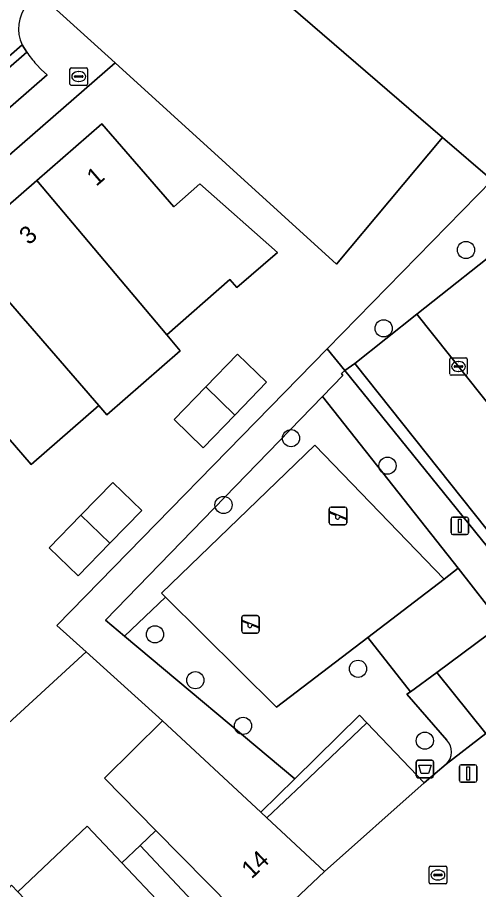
# Model space of a CAD drawing. Extents: x 161881 to 162523, y 381678 to 382381.
# Drawn here: x 162089.24 to 162115.53, y 382087.64 to 382137.32 of the extents above; entities that cross this region are included whole.
import ezdxf

# ---------------------------------------------------------------- set-up
doc = ezdxf.new("R2010")
doc.units = 0
for name, color, linetype in [('IMGEO_Afvalbak', 7, 'Continuous'), ('IMGEO_Boom', 7, 'Continuous'), ('IMGEO_Erf', 7, 'Continuous'), ('IMGEO_Groenvoorziening', 7, 'Continuous'), ('IMGEO_Hek', 7, 'Continuous'), ('IMGEO_Kolk', 7, 'Continuous'), ('IMGEO_Lichtmast', 7, 'Continuous'), ('IMGEO_Pand', 7, 'Continuous'), ('IMGEO_Pand_nummerreeks', 7, 'Continuous'), ('IMGEO_Pand_overbouw', 7, 'Continuous'), ('IMGEO_Parkeervlak_open', 7, 'Continuous'), ('IMGEO_Rijbaan_lokaal_open', 7, 'Continuous'), ('IMGEO_Speelvoorziening', 7, 'Continuous'), ('IMGEO_Terreindeel_zand', 7, 'Continuous'), ('IMGEO_Voetpad_open', 7, 'Continuous'), ('IMGEO_Woonerf_open', 7, 'Continuous')]:
    doc.layers.add(name, color=color, linetype=linetype)

msp = doc.modelspace()

# ---------------------------------------------------------------- linework, layer by layer
at = {"layer": 'IMGEO_Afvalbak'}
for p, q in [((162111.976, 382094.108), (162111.976, 382094.908)), ((162111.976, 382094.908), (162111.976, 382094.108)), ((162112.076, 382095.008), (162112.866, 382095.008)), ((162112.866, 382095.008), (162112.076, 382095.008)), ((162112.966, 382094.908), (162112.966, 382094.108)), ((162112.966, 382094.108), (162112.966, 382094.908)), ((162112.866, 382094.008), (162112.076, 382094.008)), ((162112.076, 382094.008), (162112.866, 382094.008))]:
    msp.add_line(p, q, dxfattribs=at)
msp.add_lwpolyline([(162112.119, 382094.722), (162112.823, 382094.722), (162112.674, 382094.252), (162112.268, 382094.252), (162112.119, 382094.722)], dxfattribs=at)
for centre, start, end in [((162112.076, 382094.908), 90, 180), ((162112.076, 382094.908), 90, 180), ((162112.866, 382094.908), 0, 90), ((162112.866, 382094.908), 360, 90), ((162112.076, 382094.108), 180, 270), ((162112.076, 382094.108), 180, 270), ((162112.866, 382094.108), 270, 0), ((162112.866, 382094.108), 270, 0)]:
    msp.add_arc(centre, 0.1, start, end, dxfattribs=at)
at = {"layer": 'IMGEO_Boom'}
for centre in [(162114.816, 382124.076), (162110.121, 382119.608), (162104.84, 382113.352), (162110.34, 382111.786), (162100.992, 382109.55), (162097.081, 382102.174), (162108.659, 382100.216), (162099.384, 382099.563), (162102.103, 382096.961), (162112.468, 382096.118)]:
    msp.add_circle(centre, 0.489, dxfattribs=at)
at = {"layer": 'IMGEO_Erf'}
for points in [[(162116.187, 382169.927), (162097.305, 382146.167), (162098.125, 382145.533), (162097.277, 382144.452), (162113.475, 382130.48), (162116.309, 382128.058)], [(162084.713, 382093.447), (162093.161, 382101.174), (162091.485, 382102.685), (162106.899, 382118.44), (162116.309, 382128.058), (162113.475, 382130.48), (162107.435, 382123.266), (162094.812, 382134.731), (162045.016, 382091.412)], [(162086.012, 382124.267), (162090.338, 382128.029), (162094.053, 382131.261), (162098.156, 382126.533), (162099.648, 382127.839), (162104.067, 382123.934), (162101.751, 382121.938), (162101.356, 382122.39), (162097.758, 382119.243), (162098.524, 382118.336), (162094.336, 382114.689), (162093.878, 382115.216), (162090.02, 382111.857), (162088.706, 382113.366)], [(162102.969, 382085.099), (162097.133, 382091.008), (162094.202, 382093.977), (162097.513, 382097.25), (162093.161, 382101.174), (162084.713, 382093.447), (162084.873, 382093.288), (162083.164, 382091.402), (162082.836, 382091.728), (162082.663, 382091.572), (162066.905, 382077.16)], [(162086.522, 382085.22), (162088.893, 382087.889), (162089.263, 382087.5), (162093.223, 382091.242), (162095.194, 382089.156), (162097.49, 382086.726)]]:
    msp.add_lwpolyline(points, dxfattribs=at)
for points in [[(162099.984, 382116.273), (162101.79, 382118.138), (162103.437, 382116.541), (162101.635, 382114.674), (162099.835, 382112.81), (162098.178, 382114.409)], [(162094.674, 382110.831), (162096.324, 382109.236), (162094.504, 382107.365), (162092.695, 382105.507), (162091.043, 382107.115), (162092.859, 382108.973)]]:
    msp.add_lwpolyline(points, close=True, dxfattribs=at)
at = {"layer": 'IMGEO_Groenvoorziening'}
for points in [[(162132.956, 382116.323), (162132.796, 382116.521), (162129.478, 382119.862), (162126.569, 382122.976), (162126.247, 382123.32), (162123.474, 382126.921), (162120.058, 382131.359), (162116.536, 382127.884), (162116.309, 382128.058), (162106.899, 382118.44), (162107.907, 382117.216), (162108.469, 382117.615), (162112.012, 382120.419), (162117.385, 382124.671), (162120.906, 382127.458), (162133.886, 382111.152), (162130.444, 382108.362), (162129.686, 382107.748), (162130.473, 382106.822), (162136.002, 382111.248), (162136.61, 382110.616), (162137.218, 382111.056)], [(162095.334, 382102.076), (162094.256, 382102.976), (162106.628, 382115.719), (162107.794, 382116.925), (162107.71, 382117.031), (162107.907, 382117.216), (162106.899, 382118.44), (162091.485, 382102.685), (162093.161, 382101.174), (162097.513, 382097.25), (162103.117, 382092.038), (162105.064, 382093.949)], [(162114.38, 382105.944), (162106.628, 382115.719), (162094.256, 382102.976), (162095.334, 382102.076), (162097.688, 382104.296), (162097.457, 382104.526), (162106.206, 382112.964), (162113.565, 382105.319)]]:
    msp.add_lwpolyline(points, close=True, dxfattribs=at)
for points in [[(162117.466, 382096.317), (162118.006, 382096.754), (162117.215, 382097.756), (162119.049, 382099.221), (162119.843, 382098.237), (162119.991, 382098.357), (162121.505, 382099.58), (162122.028, 382100.003), (162126.539, 382103.647), (162125.726, 382104.611), (162125.058, 382104.075), (162121.513, 382101.233), (162121.424, 382101.345), (162121, 382101.024), (162107.907, 382117.216), (162107.71, 382117.031), (162107.794, 382116.925), (162106.628, 382115.719), (162114.38, 382105.944), (162116.87, 382102.749), (162113.15, 382100.011), (162115.951, 382096.535)], [(162111.445, 382098.77), (162111.653, 382098.909), (162109.226, 382101.989), (162104.008, 382098.021), (162097.688, 382104.296), (162095.334, 382102.076), (162105.064, 382093.949), (162108.747, 382097.564), (162109.165, 382097.128), (162112.431, 382093.718), (162113.69, 382094.776)], [(162113.725, 382096.155), (162111.445, 382098.77)]]:
    msp.add_lwpolyline(points, dxfattribs=at)
msp.add_arc((162113.018, 382095.483), 0.976, 313.5594, 43.5328, dxfattribs=at)
at = {"layer": 'IMGEO_Hek'}
for points in [[(162106.899, 382118.44), (162107.907, 382117.216)], [(162107.907, 382117.216), (162107.71, 382117.031), (162107.794, 382116.925)]]:
    msp.add_lwpolyline(points, dxfattribs=at)
at = {"layer": 'IMGEO_Kolk'}
for p, q in [((162092.231, 382133.53), (162092.231, 382134.382)), ((162092.306, 382134.456), (162093.158, 382134.456)), ((162092.719, 382134.236), (162092.744, 382134.236)), ((162093.232, 382134.382), (162093.232, 382133.53)), ((162092.49, 382133.95), (162092.49, 382133.962)), ((162092.928, 382133.913), (162092.53, 382133.913)), ((162092.533, 382133.999), (162092.931, 382133.999)), ((162092.742, 382133.676), (162092.717, 382133.676)), ((162092.974, 382133.962), (162092.974, 382133.95)), ((162093.158, 382133.456), (162092.306, 382133.456)), ((162113.889, 382117.01), (162113.889, 382117.862)), ((162113.964, 382117.936), (162114.816, 382117.936)), ((162114.89, 382117.862), (162114.89, 382117.01)), ((162114.148, 382117.43), (162114.148, 382117.442)), ((162114.586, 382117.393), (162114.188, 382117.393)), ((162114.191, 382117.479), (162114.589, 382117.479)), ((162114.377, 382117.716), (162114.402, 382117.716)), ((162114.632, 382117.442), (162114.632, 382117.43)), ((162114.816, 382116.936), (162113.964, 382116.936)), ((162114.4, 382117.156), (162114.375, 382117.156)), ((162112.792, 382088.966), (162113.644, 382088.966)), ((162112.717, 382088.04), (162112.717, 382088.892)), ((162112.976, 382088.46), (162112.976, 382088.472)), ((162113.414, 382088.423), (162113.016, 382088.423)), ((162113.019, 382088.509), (162113.417, 382088.509)), ((162113.205, 382088.746), (162113.23, 382088.746)), ((162113.46, 382088.472), (162113.46, 382088.46)), ((162113.718, 382088.892), (162113.718, 382088.04)), ((162113.644, 382087.966), (162112.792, 382087.966)), ((162113.228, 382088.186), (162113.203, 382088.186))]:
    msp.add_line(p, q, dxfattribs=at)
for points in [[(162092.231, 382133.53), (162092.231, 382134.382)], [(162092.306, 382134.456), (162093.158, 382134.456)], [(162093.232, 382134.382), (162093.232, 382133.53)], [(162093.158, 382133.456), (162092.306, 382133.456)], [(162113.889, 382117.01), (162113.889, 382117.862)], [(162113.964, 382117.936), (162114.816, 382117.936)], [(162114.89, 382117.862), (162114.89, 382117.01)], [(162114.816, 382116.936), (162113.964, 382116.936)], [(162112.792, 382088.966), (162113.644, 382088.966)], [(162112.717, 382088.04), (162112.717, 382088.892)], [(162113.718, 382088.892), (162113.718, 382088.04)], [(162113.644, 382087.966), (162112.792, 382087.966)]]:
    msp.add_lwpolyline(points, dxfattribs=at)
for centre, radius, start, end in [((162092.308, 382134.38), 0.0765, 91.552, 178.448), ((162092.308, 382134.38), 0.0765, 91.552, 178.448), ((162093.156, 382134.38), 0.0765, 1.552, 88.448), ((162093.156, 382134.38), 0.0765, 1.552, 88.448), ((162092.53, 382133.959), 0.0403, 85.8775, 175.7526), ((162092.527, 382133.949), 0.0366, 178.938, 274.7102), ((162092.931, 382133.956), 0.043, 264.8664, 352.4533), ((162092.935, 382133.961), 0.0386, 1.7309, 96.639), ((162092.308, 382133.532), 0.0765, 181.552, 268.448), ((162092.308, 382133.532), 0.0765, 181.552, 268.448), ((162093.156, 382133.532), 0.0765, 271.552, 358.448), ((162093.156, 382133.532), 0.0765, 271.552, 358.448), ((162113.966, 382117.86), 0.0765, 91.552, 178.448), ((162113.966, 382117.86), 0.0765, 91.552, 178.448), ((162114.814, 382117.86), 0.0765, 1.552, 88.448), ((162114.814, 382117.86), 0.0765, 1.552, 88.448), ((162114.188, 382117.439), 0.0403, 85.8775, 175.7526), ((162114.185, 382117.429), 0.0366, 178.938, 274.7102), ((162114.589, 382117.436), 0.043, 264.8664, 352.4533), ((162114.593, 382117.441), 0.0386, 1.7309, 96.639), ((162113.966, 382117.012), 0.0765, 181.552, 268.448), ((162113.966, 382117.012), 0.0765, 181.552, 268.448), ((162114.814, 382117.012), 0.0765, 271.552, 358.448), ((162114.814, 382117.012), 0.0765, 271.552, 358.448), ((162112.794, 382088.89), 0.0765, 91.552, 178.448), ((162112.794, 382088.89), 0.0765, 91.552, 178.448), ((162113.642, 382088.89), 0.0765, 1.552, 88.448), ((162113.642, 382088.89), 0.0765, 1.552, 88.448), ((162113.016, 382088.469), 0.0403, 85.8775, 175.7526), ((162113.013, 382088.459), 0.0366, 178.938, 274.7102), ((162113.417, 382088.466), 0.043, 264.8664, 352.4533), ((162113.421, 382088.471), 0.0386, 1.7309, 96.639), ((162112.794, 382088.042), 0.0765, 181.552, 268.448), ((162112.794, 382088.042), 0.0765, 181.552, 268.448), ((162113.642, 382088.042), 0.0765, 271.552, 358.448), ((162113.642, 382088.042), 0.0765, 271.552, 358.448)]:
    msp.add_arc(centre, radius, start, end, dxfattribs=at)
for centre, major_axis, ratio, start_param, end_param in [((162092.718, 382133.956), (-0.387, 0.002), 0.722429, 4.712389, 7.853982), ((162092.743, 382133.956), (-0.39, 0.002), 0.717154, 1.570796, 4.712389), ((162114.376, 382117.436), (-0.387, 0.002), 0.722429, 4.712389, 7.853982), ((162114.401, 382117.436), (-0.39, 0.002), 0.717154, 1.570796, 4.712389), ((162113.204, 382088.466), (-0.387, 0.002), 0.722429, 4.712389, 7.853982), ((162113.229, 382088.466), (-0.39, 0.002), 0.717154, 1.570796, 4.712389)]:
    msp.add_ellipse(centre, major_axis=major_axis, ratio=ratio, start_param=start_param, end_param=end_param, dxfattribs=at)
at = {"layer": 'IMGEO_Lichtmast'}
for p, q in [((162114.064, 382108.862), (162114.854, 382108.862)), ((162114.854, 382108.862), (162114.064, 382108.862)), ((162113.964, 382107.962), (162113.964, 382108.762)), ((162113.964, 382108.762), (162113.964, 382107.962)), ((162114.954, 382108.762), (162114.954, 382107.962)), ((162114.954, 382107.962), (162114.954, 382108.762)), ((162114.854, 382107.862), (162114.064, 382107.862)), ((162114.064, 382107.862), (162114.854, 382107.862)), ((162114.439, 382093.847), (162114.439, 382094.647)), ((162114.439, 382094.647), (162114.439, 382093.847)), ((162114.539, 382094.747), (162115.329, 382094.747)), ((162115.329, 382094.747), (162114.539, 382094.747)), ((162115.429, 382094.647), (162115.429, 382093.847)), ((162115.429, 382093.847), (162115.429, 382094.647)), ((162115.329, 382093.747), (162114.539, 382093.747)), ((162114.539, 382093.747), (162115.329, 382093.747))]:
    msp.add_line(p, q, dxfattribs=at)
for points in [[(162114.384, 382108.737), (162114.534, 382108.737), (162114.534, 382107.987), (162114.384, 382107.987), (162114.384, 382108.737)], [(162114.859, 382094.622), (162115.009, 382094.622), (162115.009, 382093.872), (162114.859, 382093.872), (162114.859, 382094.622)]]:
    msp.add_lwpolyline(points, dxfattribs=at)
for centre, start, end in [((162114.064, 382108.762), 90, 180), ((162114.064, 382108.762), 90, 180), ((162114.854, 382108.762), 0, 90), ((162114.854, 382108.762), 360, 90), ((162114.064, 382107.962), 180, 270), ((162114.064, 382107.962), 180, 270), ((162114.854, 382107.962), 270, 0), ((162114.854, 382107.962), 270, 0), ((162114.539, 382094.647), 90, 180), ((162114.539, 382094.647), 90, 180), ((162115.329, 382094.647), 0, 90), ((162115.329, 382094.647), 360, 90), ((162114.539, 382093.847), 180, 270), ((162114.539, 382093.847), 180, 270), ((162115.329, 382093.847), 270, 0), ((162115.329, 382093.847), 270, 0)]:
    msp.add_arc(centre, 0.1, start, end, dxfattribs=at)
at = {"layer": 'IMGEO_Pand'}
for points in [[(162097.277, 382144.452), (162097.156, 382144.557), (162091.265, 382137.952), (162094.812, 382134.731), (162107.435, 382123.266), (162113.475, 382130.48)], [(162098.156, 382126.533), (162094.053, 382131.261), (162090.338, 382128.029), (162097.758, 382119.243), (162101.356, 382122.39), (162101.751, 382121.938), (162104.067, 382123.934), (162099.648, 382127.839)], [(162090.338, 382128.029), (162086.012, 382124.267), (162093.878, 382115.216), (162094.336, 382114.689), (162098.524, 382118.336), (162097.758, 382119.243)], [(162086.012, 382124.267), (162082.144, 382120.902), (162088.706, 382113.366), (162090.02, 382111.857), (162093.878, 382115.216)], [(162101.79, 382118.138), (162099.984, 382116.273), (162101.635, 382114.674), (162103.437, 382116.541)], [(162101.635, 382114.674), (162099.984, 382116.273), (162098.178, 382114.409), (162099.835, 382112.81)], [(162094.674, 382110.831), (162092.859, 382108.973), (162094.504, 382107.365), (162096.324, 382109.236)], [(162092.859, 382108.973), (162091.043, 382107.115), (162092.695, 382105.507), (162094.504, 382107.365)], [(162103.466, 382091.714), (162103.117, 382092.038), (162097.513, 382097.25), (162094.202, 382093.977), (162097.133, 382091.008), (162102.969, 382085.099), (162106.745, 382088.664)], [(162097.49, 382086.726), (162095.194, 382089.156), (162093.223, 382091.242), (162089.263, 382087.5), (162096.989, 382079.376), (162100.923, 382083.091)]]:
    msp.add_lwpolyline(points, close=True, dxfattribs=at)
at = {"layer": 'IMGEO_Pand_overbouw'}
for points in [[(162097.133, 382091.009), (162096.23, 382090.146), (162101.946, 382084.095), (162102.969, 382085.099)], [(162095.194, 382089.156), (162097.49, 382086.726), (162100.923, 382083.091), (162101.946, 382084.095), (162096.23, 382090.146)]]:
    msp.add_lwpolyline(points, close=True, dxfattribs=at)
at = {"layer": 'IMGEO_Parkeervlak_open'}
for points in [[(162089.765, 382135.352), (162060.132, 382109.524)], [(162060.865, 382109.155), (162061.499, 382108.414), (162090.927, 382134.045), (162090.608, 382134.346), (162090.308, 382134.665)]]:
    msp.add_lwpolyline(points, dxfattribs=at)
for points in [[(162125.058, 382104.075), (162112.012, 382120.419), (162108.469, 382117.615), (162121.424, 382101.345), (162121.513, 382101.233)], [(162109.165, 382097.128), (162108.747, 382097.564), (162105.064, 382093.949), (162103.117, 382092.038), (162103.466, 382091.714), (162105.466, 382093.613)], [(162112.431, 382093.718), (162109.165, 382097.128), (162105.466, 382093.613), (162103.466, 382091.714), (162106.745, 382088.664)]]:
    msp.add_lwpolyline(points, close=True, dxfattribs=at)
msp.add_arc((162095.598, 382139.404), 7.103, 214.7883, 221.8569, dxfattribs=at)
at = {"layer": 'IMGEO_Rijbaan_lokaal_open'}
for points in [[(162080.253, 382135.078), (162068.499, 382124.843), (162062.239, 382119.267), (162037.797, 382098.117), (162037.509, 382098.473), (162034.321, 382102.015), (162033.172, 382100.991), (162033.004, 382100.842), (162039.632, 382091.47), (162041.229, 382092.869), (162042.236, 382091.698), (162043.757, 382093.013), (162042.637, 382094.281), (162042.331, 382094.626), (162089.5, 382135.76)], [(162089.765, 382135.352), (162089.5, 382135.76), (162042.331, 382094.626), (162042.637, 382094.281), (162057.277, 382107.051)], [(162060.132, 382109.524), (162089.765, 382135.352)], [(162113.15, 382100.011), (162111.653, 382098.909), (162111.445, 382098.77), (162113.725, 382096.155)], [(162113.69, 382094.776), (162115.951, 382096.535), (162113.15, 382100.011)]]:
    msp.add_lwpolyline(points, dxfattribs=at)
msp.add_lwpolyline([(162117.385, 382124.671), (162112.012, 382120.419), (162125.058, 382104.075), (162125.726, 382104.611), (162126.539, 382103.647), (162130.473, 382106.822), (162129.686, 382107.748), (162130.444, 382108.362)], close=True, dxfattribs=at)
for centre, radius, start, end in [((162091.447, 382136.673), 2.15, 140.5225, 205.1285), ((162113.018, 382095.483), 0.976, 313.5594, 43.5328)]:
    msp.add_arc(centre, radius, start, end, dxfattribs=at)
at = {"layer": 'IMGEO_Speelvoorziening'}
for p, q in [((162107.023, 382108.525), (162107.023, 382109.325)), ((162107.023, 382109.325), (162107.023, 382108.525)), ((162107.123, 382109.425), (162107.913, 382109.425)), ((162107.913, 382109.425), (162107.123, 382109.425)), ((162108.013, 382109.325), (162108.013, 382108.525)), ((162108.013, 382108.525), (162108.013, 382109.325)), ((162107.406, 382108.953), (162107.067, 382109.09)), ((162107.092, 382109.15), (162107.968, 382108.797)), ((162107.944, 382108.737), (162107.604, 382108.874)), ((162107.913, 382108.425), (162107.123, 382108.425)), ((162107.123, 382108.425), (162107.913, 382108.425)), ((162102.026, 382102.35), (162102.026, 382103.15)), ((162102.026, 382103.15), (162102.026, 382102.35)), ((162102.409, 382102.778), (162102.07, 382102.915)), ((162102.095, 382102.975), (162102.971, 382102.622)), ((162102.126, 382103.25), (162102.916, 382103.25)), ((162102.916, 382103.25), (162102.126, 382103.25)), ((162103.016, 382103.15), (162103.016, 382102.35)), ((162103.016, 382102.35), (162103.016, 382103.15)), ((162102.947, 382102.562), (162102.607, 382102.699)), ((162102.916, 382102.25), (162102.126, 382102.25)), ((162102.126, 382102.25), (162102.916, 382102.25))]:
    msp.add_line(p, q, dxfattribs=at)
for centre, radius, start, end in [((162107.123, 382109.325), 0.1, 90, 180), ((162107.123, 382109.325), 0.1, 90, 180), ((162107.913, 382109.325), 0.1, 0, 90), ((162107.913, 382109.325), 0.1, 360, 90), ((162107.08, 382109.12), 0.0327, 68.078, 248.078), ((162107.485, 382108.863), 0.12, 130.9928, 5.1632), ((162107.956, 382108.767), 0.0327, 248.078, 68.078), ((162107.123, 382108.525), 0.1, 180, 270), ((162107.123, 382108.525), 0.1, 180, 270), ((162107.913, 382108.525), 0.1, 270, 0), ((162107.913, 382108.525), 0.1, 270, 0), ((162102.126, 382103.15), 0.1, 90, 180), ((162102.126, 382103.15), 0.1, 90, 180), ((162102.083, 382102.945), 0.0327, 68.078, 248.078), ((162102.916, 382103.15), 0.1, 0, 90), ((162102.916, 382103.15), 0.1, 360, 90), ((162102.126, 382102.35), 0.1, 180, 270), ((162102.126, 382102.35), 0.1, 180, 270), ((162102.488, 382102.688), 0.12, 130.9928, 5.1632), ((162102.916, 382102.35), 0.1, 270, 0), ((162102.916, 382102.35), 0.1, 270, 0), ((162102.959, 382102.592), 0.0327, 248.078, 68.078)]:
    msp.add_arc(centre, radius, start, end, dxfattribs=at)
at = {"layer": 'IMGEO_Terreindeel_zand'}
msp.add_lwpolyline([(162097.688, 382104.296), (162104.008, 382098.021), (162109.226, 382101.989), (162113.565, 382105.319), (162106.206, 382112.964), (162097.457, 382104.526)], close=True, dxfattribs=at)
at = {"layer": 'IMGEO_Voetpad_open'}
for points in [[(162094.812, 382134.731), (162091.265, 382137.952), (162090.363, 382138.772), (162090.245, 382138.622), (162089.787, 382138.04)], [(162089.5, 382135.76), (162089.765, 382135.352)], [(162090.308, 382134.665), (162090.608, 382134.346), (162090.927, 382134.045), (162061.499, 382108.414), (162061.496, 382108.207), (162060.797, 382107.623), (162059.375, 382109.235), (162057.984, 382108.023), (162059.407, 382106.418), (162058.417, 382105.55), (162058.2, 382105.55), (162043.757, 382093.013), (162042.236, 382091.698), (162042.306, 382091.549), (162043.519, 382090.148), (162045.016, 382091.412), (162094.812, 382134.731)]]:
    msp.add_lwpolyline(points, dxfattribs=at)
for points in [[(162121.424, 382101.345), (162108.469, 382117.615), (162107.907, 382117.216), (162121, 382101.024)], [(162111.653, 382098.909), (162113.15, 382100.011), (162116.87, 382102.749), (162114.38, 382105.944), (162113.565, 382105.319), (162109.226, 382101.989)]]:
    msp.add_lwpolyline(points, close=True, dxfattribs=at)
for centre, radius, start, end in [((162091.447, 382136.673), 2.15, 140.5225, 205.1285), ((162095.598, 382139.404), 7.103, 214.7883, 221.8569)]:
    msp.add_arc(centre, radius, start, end, dxfattribs=at)
at = {"layer": 'IMGEO_Woonerf_open'}
msp.add_lwpolyline([(162115.951, 382096.535), (162113.69, 382094.776), (162112.431, 382093.718), (162106.745, 382088.664), (162102.969, 382085.099)], dxfattribs=at)

# ---------------------------------------------------------------- texts
at = {"layer": 'IMGEO_Pand_nummerreeks'}
for s, rotation, p in [('1', 40.8175, (162093.727, 382127.665)), ('3', 40.8175, (162089.882, 382124.321)), ('14', 43.3557, (162102.592, 382088.208))]:
    msp.add_text(s, height=1, rotation=rotation, dxfattribs=at).set_placement(p)

doc.saveas('drawing.dxf')
